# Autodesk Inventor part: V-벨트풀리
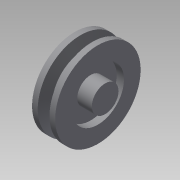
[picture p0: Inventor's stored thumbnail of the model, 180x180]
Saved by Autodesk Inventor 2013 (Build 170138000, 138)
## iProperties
Created: 2015-02
Part Number: V-벨트풀리
Material: 일반
Document SubType Name: Modeling
Designer: Administrator
Density: 1 g/cm^3
Author: Administrator
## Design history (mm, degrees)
sketch "스케치1"
  geometry: L1 (0, 0)-(25, 0); L2 (0, 0)-(0, 11); L3 (0, 11)-(6, 11); L4 (6, 11)-(6, 21.5); L5 (6, 21.5)-(0, 21.5); L6 (0, 21.5)-(0, 35.2); L7 (0, 35.2)-(4.675, 35.2); L8 (4.675, 35.2)-(7.426, 26.2); L9 (7.426, 26.2)-(11.574, 26.2); L10 (11.574, 26.2)-(14.325, 35.2); L11 (14.325, 35.2)-(19, 35.2); L12 (19, 35.2)-(19, 21.5); L13 (19, 21.5)-(13, 21.5); L14 (13, 21.5)-(13, 11); L15 (13, 11)-(25, 11); L16 (25, 11)-(25, 0); L17 (5.5, 32.5)-(13.5, 32.5); 1 further point
  constraints: 34 end point, 8 perpendicular, 5 equal length, 5 parallel, 2 collinear, 2 point on line, 1 horizontal, 1 midpoint, 1 vertical alignment
  dimensions: "d0" = 25 distance of L1.start L1.end; "d1" = 43 diameter of L5 L1; "d2" = 65 diameter of L17 L1; "d3" = 19 distance between parallel lines of L12 L6; "d4" = 8 distance of L17.start L17.end; "d5" = 34 deg angle of L10 L8; "d6" = 6 distance between parallel lines of L4 L2; "d7" = 6.3 distance between parallel lines of L17 L9; "d8" = 2.7 distance between parallel lines of L11 L17; "d9" = 22 diameter of L15 L1
revolve "회전1" sketch "스케치1" stored, may be unused: angle "d10" = 90 deg
node "솔리드1"
